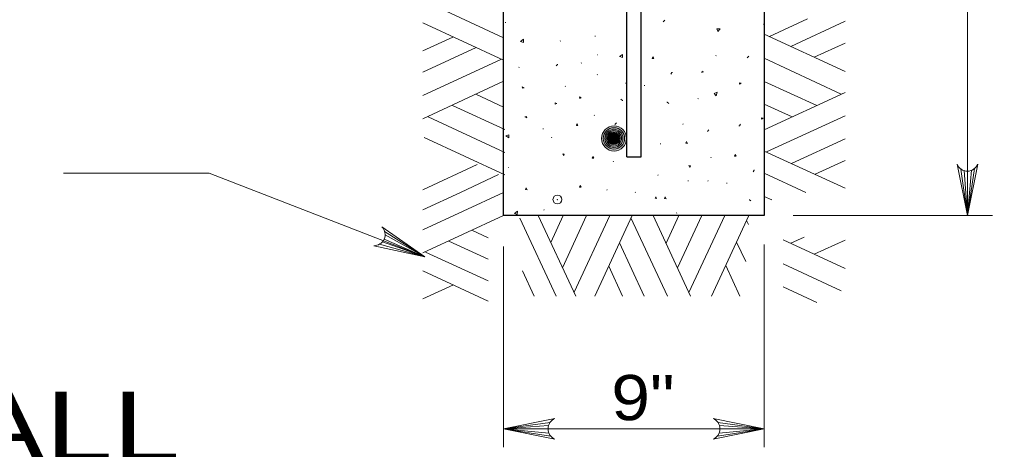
# Model space of a CAD drawing. Extents: x 1083.1 to 1117.1, y 697.4 to 741.4.
# Drawn here: x 1108.478 to 1111.836, y 721.161 to 722.646 of the extents above; entities that cross this region are included whole.
import ezdxf
from ezdxf.enums import TextEntityAlignment as Align

# ---------------------------------------------------------------- set-up
doc = ezdxf.new("R2010")
doc.units = 0
doc.header["$LTSCALE"] = 0.062
doc.header["$PDMODE"] = 32
doc.header["$PDSIZE"] = 0.031
doc.layers.add('1', color=7, linetype='Continuous', lineweight=13)

msp = doc.modelspace()

# ---------------------------------------------------------------- hatches: boundary and pattern name
at = {"layer": '1'}
h = msp.add_hatch(color=256, dxfattribs=at)
edge = h.paths.add_edge_path()
edge.add_ellipse((1110.52988, 722.23524), major_axis=(0.04324, 0), ratio=0.9998948, start_angle=0, end_angle=360)
h = msp.add_hatch(color=256, dxfattribs=at)
edge = h.paths.add_edge_path()
edge.add_ellipse((1110.52957, 722.23545), major_axis=(0.03676, 0), ratio=0.9998948, start_angle=0, end_angle=360)
h = msp.add_hatch(color=256, dxfattribs=at)
edge = h.paths.add_edge_path()
edge.add_ellipse((1110.5293, 722.23563), major_axis=(0.03124, 0), ratio=0.9998948, start_angle=0, end_angle=360)
h = msp.add_hatch(color=256, dxfattribs=at)
edge = h.paths.add_edge_path()
edge.add_ellipse((1110.52907, 722.23578), major_axis=(0.02656, 0), ratio=0.9998948, start_angle=0, end_angle=360)
h = msp.add_hatch(color=256, dxfattribs=at)
edge = h.paths.add_edge_path()
edge.add_ellipse((1110.52888, 722.23591), major_axis=(0.02257, 0), ratio=0.9998948, start_angle=0, end_angle=360)
h = msp.add_hatch(color=256, dxfattribs=at)
edge = h.paths.add_edge_path()
edge.add_ellipse((1110.52872, 722.23611), major_axis=(0.01919, 0), ratio=0.9998948, start_angle=0, end_angle=360)
h = msp.add_hatch(color=256, dxfattribs=at)
edge = h.paths.add_edge_path()
edge.add_ellipse((1110.52858, 722.23628), major_axis=(0.01631, 0), ratio=0.9998948, start_angle=0, end_angle=360)
h = msp.add_hatch(color=256, dxfattribs=at)
edge = h.paths.add_edge_path()
edge.add_ellipse((1110.52846, 722.23643), major_axis=(0.01386, 0), ratio=0.9998948, start_angle=0, end_angle=360)
h = msp.add_hatch(color=256, dxfattribs=at)
edge = h.paths.add_edge_path()
edge.add_ellipse((1110.52836, 722.23655), major_axis=(0.01178, 0), ratio=0.9998948, start_angle=0, end_angle=360)
h = msp.add_hatch(color=256, dxfattribs=at)
edge = h.paths.add_edge_path()
edge.add_ellipse((1110.52827, 722.23665), major_axis=(0.01002, 0), ratio=0.9998948, start_angle=0, end_angle=360)
h = msp.add_hatch(color=256, dxfattribs=at)
edge = h.paths.add_edge_path()
edge.add_ellipse((1110.52812, 722.23674), major_axis=(0.00851, 0), ratio=0.9998948, start_angle=0, end_angle=360)
h = msp.add_hatch(color=256, dxfattribs=at)
edge = h.paths.add_edge_path()
edge.add_ellipse((1110.52791, 722.23682), major_axis=(0.00724, 0), ratio=0.9998948, start_angle=0, end_angle=360)
h = msp.add_hatch(color=256, dxfattribs=at)
edge = h.paths.add_edge_path()
edge.add_ellipse((1110.52789, 722.23688), major_axis=(0.00615, 0), ratio=0.9998948, start_angle=0, end_angle=360)
h = msp.add_hatch(color=256, dxfattribs=at)
edge = h.paths.add_edge_path()
edge.add_ellipse((1110.52787, 722.23693), major_axis=(0.00523, 0), ratio=0.9998948, start_angle=0, end_angle=360)
h = msp.add_hatch(color=256, dxfattribs=at)
edge = h.paths.add_edge_path()
edge.add_ellipse((1110.52786, 722.23689), major_axis=(0.00444, 0), ratio=0.9998948, start_angle=0, end_angle=360)
h = msp.add_hatch(color=256, dxfattribs=at)
edge = h.paths.add_edge_path()
edge.add_ellipse((1110.52785, 722.23685), major_axis=(0.00378, 0), ratio=0.9998948, start_angle=0, end_angle=360)
h = msp.add_hatch(color=256, dxfattribs=at)
edge = h.paths.add_edge_path()
edge.add_ellipse((1110.52784, 722.23682), major_axis=(0.00321, 0), ratio=0.9998948, start_angle=0, end_angle=360)
h = msp.add_hatch(color=256, dxfattribs=at)
edge = h.paths.add_edge_path()
edge.add_ellipse((1110.52834, 722.23663), major_axis=(0.00273, 0), ratio=0.9998948, start_angle=0, end_angle=360)

# ---------------------------------------------------------------- linework, layer by layer
at = {"layer": '1', "lineweight": 25}
for p, q in [((1110.57367, 722.1715), (1110.57367, 724.62733)), ((1110.62367, 722.1715), (1110.62367, 724.62717)), ((1110.57083, 722.42675), (1110.57017, 722.42483)), ((1110.57367, 722.1715), (1110.62367, 722.1715))]:
    msp.add_line(p, q, dxfattribs=at)
at = {"layer": '1'}
for p, q in [((1110.14883, 722.58242), (1109.88425, 722.70525)), ((1110.14883, 722.5055), (1109.87042, 722.63433)), ((1110.156, 722.63575), (1110.15408, 722.635)), ((1111.046, 722.62892), (1111.04683, 722.63083)), ((1111.06575, 722.58717), (1111.19717, 722.64858)), ((1111.14008, 722.55258), (1111.32692, 722.63992)), ((1109.97333, 722.58508), (1109.87042, 722.53833)), ((1110.46433, 722.58975), (1110.465, 722.58775)), ((1111.04842, 722.59492), (1111.32692, 722.46608)), ((1110.34375, 722.57108), (1110.345, 722.57258)), ((1111.22058, 722.51542), (1111.32692, 722.56383)), ((1110.05458, 722.54875), (1109.87042, 722.464)), ((1110.47325, 722.52442), (1110.47125, 722.52367)), ((1110.88258, 722.52117), (1110.88058, 722.5205)), ((1110.14108, 722.509), (1109.87042, 722.38358)), ((1110.41717, 722.49683), (1110.41642, 722.49483)), ((1111.04842, 722.512), (1111.31392, 722.38825)), ((1110.20292, 722.48133), (1110.20092, 722.4805)), ((1110.47308, 722.45575), (1110.47108, 722.455)), ((1110.14883, 722.43283), (1109.87042, 722.30308)), ((1110.361, 722.41483), (1110.36217, 722.41633)), ((1110.63617, 722.41783), (1110.63417, 722.4185)), ((1111.04842, 722.43242), (1111.22917, 722.3485)), ((1110.14883, 722.34375), (1110.05292, 722.38783)), ((1111.04842, 722.26467), (1111.32692, 722.39433)), ((1110.15317, 722.26642), (1109.97242, 722.3495)), ((1110.81933, 722.37325), (1110.82133, 722.37258)), ((1111.04842, 722.35367), (1111.14442, 722.30958)), ((1110.46125, 722.31458), (1110.46275, 722.31567)), ((1110.15317, 722.18692), (1109.88858, 722.30967)), ((1110.76808, 722.28542), (1110.76733, 722.28342)), ((1111.05625, 722.18858), (1111.32692, 722.31392)), ((1110.286, 722.26875), (1110.284, 722.268)), ((1110.15317, 722.10992), (1109.87467, 722.23875)), ((1110.31517, 722.23967), (1110.31442, 722.23767)), ((1110.69033, 722.21775), (1110.68958, 722.21583)), ((1111.14267, 722.14883), (1111.32692, 722.23358)), ((1111.04842, 722.192), (1111.32692, 722.06317)), ((1110.52767, 722.15658), (1110.527, 722.15458)), ((1110.86517, 722.17067), (1110.86442, 722.16867)), ((1111.22392, 722.11242), (1111.32692, 722.15917)), ((1108.62958, 722.11558), (1109.13258, 722.11558)), ((1109.87667, 721.82642), (1109.13258, 722.11558)), ((1110.05717, 722.14492), (1109.87042, 722.05758)), ((1110.16525, 722.13483), (1110.16725, 722.1355)), ((1111.04842, 722.115), (1111.19125, 722.04875)), ((1111.72692, 722.12967), (1111.74933, 721.96942)), ((1111.738, 722.12425), (1111.74933, 721.96942)), ((1111.77408, 722.1315), (1111.74933, 721.96942)), ((1111.76367, 722.12542), (1111.74933, 721.96942)), ((1111.74933, 722.12258), (1111.74933, 721.96942)), ((1110.13158, 722.11033), (1110.00017, 722.04892)), ((1110.68225, 722.10958), (1110.68142, 722.10758)), ((1110.78608, 722.08967), (1110.78533, 722.08767)), ((1110.85475, 722.08975), (1110.854, 722.08783)), ((1110.92008, 722.08083), (1110.91808, 722.0815)), ((1110.00017, 722.04892), (1109.87042, 721.98925)), ((1110.14883, 722.04892), (1109.87042, 721.92008)), ((1110.506, 722.05925), (1110.50517, 722.05725)), ((1110.60242, 722.04867), (1110.60392, 722.04983)), ((1111.04842, 722.0355), (1111.07442, 722.02358)), ((1110.2885, 721.98975), (1110.28767, 721.98792)), ((1110.14883, 721.96942), (1109.87042, 721.84058)), ((1110.20442, 721.96067), (1110.32975, 721.69092)), ((1110.2675, 721.96942), (1110.39817, 721.69092)), ((1110.35408, 721.96942), (1110.31167, 721.87608)), ((1110.43533, 721.96942), (1110.35225, 721.78867)), ((1110.51492, 721.96942), (1110.39208, 721.70483)), ((1110.59183, 721.96942), (1110.463, 721.69092)), ((1110.58833, 721.96158), (1110.71383, 721.69092)), ((1110.6645, 721.96942), (1110.79417, 721.69092)), ((1110.75358, 721.96942), (1110.7095, 721.87342)), ((1110.74508, 721.97758), (1110.74667, 721.97867)), ((1110.83225, 721.96942), (1110.74842, 721.78867)), ((1110.91183, 721.96942), (1110.78817, 721.70392)), ((1110.99483, 721.96942), (1110.86592, 721.69092)), ((1110.98708, 721.95208), (1110.99375, 721.93775)), ((1111.14842, 721.96942), (1111.836, 721.96942)), ((1109.73825, 721.91425), (1109.87667, 721.82642)), ((1110.09525, 721.89275), (1110.039, 721.91842)), ((1109.7365, 721.888), (1109.87667, 721.82642)), ((1109.73967, 721.90233), (1109.87667, 721.82642)), ((1110.09525, 721.81917), (1109.95942, 721.88125)), ((1111.11375, 721.88567), (1111.32692, 721.78692)), ((1111.14008, 721.87342), (1111.18608, 721.89492)), ((1111.22058, 721.83625), (1111.32692, 721.88467)), ((1109.721, 721.87033), (1109.87667, 721.82642)), ((1109.73042, 721.87825), (1109.87667, 721.82642)), ((1110.14883, 721.86292), (1110.14883, 721.16983)), ((1110.54858, 721.87517), (1110.63333, 721.69092)), ((1110.9525, 721.87775), (1110.98408, 721.81008)), ((1111.04842, 721.86942), (1111.04842, 721.16983)), ((1110.09525, 721.74333), (1109.87908, 721.84317)), ((1110.09525, 721.67417), (1109.8695, 721.77833)), ((1110.21442, 721.778), (1110.25458, 721.69092)), ((1110.51233, 721.79392), (1110.559, 721.69092)), ((1110.91533, 721.79733), (1110.96367, 721.69092)), ((1111.11375, 721.80242), (1111.31392, 721.70917)), ((1109.97592, 721.72983), (1109.87042, 721.6815)), ((1111.11375, 721.72292), (1111.22917, 721.66933)), ((1110.30908, 721.25533), (1110.14883, 721.23292)), ((1110.30367, 721.24425), (1110.14883, 721.23292)), ((1110.88817, 721.25533), (1111.04842, 721.23292)), ((1110.89358, 721.24425), (1111.04842, 721.23292)), ((1110.14883, 721.23292), (1111.04842, 721.23292)), ((1110.302, 721.23292), (1110.14883, 721.23292)), ((1110.30483, 721.2185), (1110.14883, 721.23292)), ((1110.311, 721.20808), (1110.14883, 721.23292)), ((1110.88633, 721.20808), (1111.04842, 721.23292)), ((1110.89242, 721.2185), (1111.04842, 721.23292)), ((1110.89525, 721.23292), (1111.04842, 721.23292))]:
    msp.add_line(p, q, dxfattribs=at)
at = {"layer": '1', "lineweight": 25}
msp.add_lwpolyline([(1111.04842, 724.96767), (1111.04842, 721.96942), (1110.14883, 721.96942), (1110.14883, 724.368)], dxfattribs=at)
at = {"layer": '1'}
for points in [[(1111.74933, 724.96767), (1111.74933, 723.2375), (1111.74933, 721.96942)], [(1110.6995, 722.638), (1110.7, 722.63942), (1110.705, 722.64358)], [(1110.88808, 722.60425), (1110.8955, 722.61408), (1110.8845, 722.61392), (1110.888, 722.60442)], [(1110.20733, 722.57025), (1110.21725, 722.57767), (1110.217, 722.56675), (1110.2075, 722.57017)], [(1110.54917, 722.51775), (1110.559, 722.52525), (1110.55883, 722.51425), (1110.54933, 722.51767)], [(1110.98908, 722.51392), (1110.9905, 722.5145), (1110.99458, 722.51942)], [(1110.33525, 722.49208), (1110.33467, 722.49067), (1110.32975, 722.4865)], [(1110.73108, 722.463), (1110.72967, 722.46242), (1110.72558, 722.4575)], [(1110.882, 722.38275), (1110.88558, 722.39458), (1110.87533, 722.39067), (1110.88183, 722.38292)], [(1110.55917, 722.36533), (1110.55858, 722.36675), (1110.55358, 722.371)], [(1110.713, 722.36208), (1110.71358, 722.36067), (1110.71858, 722.3565)], [(1110.5385, 722.28892), (1110.53708, 722.28833), (1110.533, 722.28333)], [(1110.961, 722.27883), (1110.96242, 722.27942), (1110.96658, 722.28442)], [(1110.15667, 722.2445), (1110.16642, 722.23717), (1110.16633, 722.24817), (1110.15683, 722.24467)], [(1110.8575, 722.26483), (1110.85617, 722.26425), (1110.85192, 722.25925)], [(1111.01508, 722.126), (1111.01367, 722.12542), (1111.0095, 722.1205)], [(1111.78475, 722.14642), (1111.74933, 721.96942), (1111.71392, 722.14642)], [(1110.997, 722.02508), (1110.99758, 722.02367), (1111.00242, 722.0195)], [(1110.18642, 721.9765), (1110.19625, 721.984), (1110.19608, 721.973), (1110.18667, 721.9765)], [(1109.72892, 721.93), (1109.87667, 721.82642), (1109.70042, 721.86517)], [(1110.32583, 721.1975), (1110.14883, 721.23292), (1110.32583, 721.26833)], [(1110.87142, 721.1975), (1111.04842, 721.23292), (1110.87142, 721.26833)]]:
    msp.add_lwpolyline(points, dxfattribs=at)
for points in [[(1110.66383, 722.51725), (1110.66192, 722.51167), (1110.66725, 722.511)], [(1110.839, 722.46575), (1110.83342, 722.46767), (1110.83275, 722.46242)], [(1110.96867, 722.42567), (1110.96308, 722.42767), (1110.96242, 722.42233)], [(1110.21967, 722.41033), (1110.214, 722.40842), (1110.21333, 722.41375)], [(1110.33267, 722.3555), (1110.32708, 722.3535), (1110.32625, 722.35867)], [(1110.41683, 722.37567), (1110.41125, 722.37375), (1110.4105, 722.379)], [(1110.22233, 722.3095), (1110.22792, 722.3115), (1110.22867, 722.30617)], [(1110.40183, 722.28625), (1110.39983, 722.28058), (1110.40517, 722.27992)], [(1111.04458, 722.30492), (1111.03892, 722.30692), (1111.03817, 722.30167)], [(1110.77958, 722.22458), (1110.77758, 722.21908), (1110.78283, 722.21825)], [(1110.356, 722.176), (1110.35783, 722.1815), (1110.35258, 722.18225)], [(1110.45683, 722.17325), (1110.45483, 722.16767), (1110.46008, 722.16692)], [(1110.94767, 722.18025), (1110.94575, 722.17467), (1110.95108, 722.17392)], [(1110.7915, 722.13558), (1110.79333, 722.14117), (1110.78817, 722.14192)], [(1110.22675, 722.06433), (1110.22475, 722.05875), (1110.23, 722.05808)], [(1110.4125, 722.07317), (1110.41067, 722.06767), (1110.41592, 722.06683)], [(1110.6735, 722.03417), (1110.67158, 722.02867), (1110.67692, 722.02783)], [(1110.706, 722.03333), (1110.704, 722.02783), (1110.70933, 722.02708)]]:
    msp.add_lwpolyline(points, close=True, dxfattribs=at)
for centre, start, end in [((1111.74927, 722.16069), 202.08782, 337.91395), ((1109.70154, 721.90329), 268.37007, 44.19619), ((1110.34016, 721.23294), 112.08782, 247.91395), ((1110.85714, 721.23294), 292.08605, 67.91218)]:
    msp.add_arc(centre, 0.0382, start, end, dxfattribs=at)
for centre, major_axis in [((1110.52988, 722.23524), (0.04324, 0)), ((1110.52957, 722.23545), (0.03676, 0)), ((1110.5293, 722.23563), (0.03124, 0)), ((1110.52907, 722.23578), (0.02656, 0)), ((1110.52888, 722.23591), (0.02257, 0)), ((1110.52872, 722.23611), (0.01919, 0)), ((1110.52858, 722.23628), (0.01631, 0)), ((1110.52846, 722.23643), (0.01386, 0)), ((1110.52836, 722.23655), (0.01178, 0)), ((1110.52827, 722.23665), (0.01002, 0)), ((1110.52812, 722.23674), (0.00851, 0)), ((1110.52791, 722.23682), (0.00724, 0)), ((1110.52789, 722.23688), (0.00615, 0)), ((1110.52787, 722.23693), (0.00523, 0)), ((1110.52786, 722.23689), (0.00444, 0)), ((1110.52785, 722.23685), (0.00378, 0)), ((1110.52784, 722.23682), (0.00321, 0)), ((1110.52834, 722.23663), (0.00273, 0))]:
    msp.add_ellipse(centre, major_axis=major_axis, ratio=0.999895, dxfattribs=at)
msp.add_point((1110.33467, 722.02458), dxfattribs=at)

# ---------------------------------------------------------------- texts
at = {"layer": '1', "width": 1.15}
msp.add_text('9"', height=0.156, dxfattribs=at).set_placement((1110.62958, 721.26283), align=Align.CENTER)
at = {"layer": '1', "width": 1.3}
msp.add_text('RIPRAP CUTOFF WALL', height=0.24, dxfattribs=at).set_placement((1104.419, 721.12125))

doc.saveas('drawing.dxf')
